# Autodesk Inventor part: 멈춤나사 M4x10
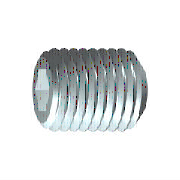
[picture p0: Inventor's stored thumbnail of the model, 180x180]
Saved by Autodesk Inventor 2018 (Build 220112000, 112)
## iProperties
Created: 2012-02
Part Number: 멈춤나사 M4x10
Material: 강철, 연강
Description: 6각 소켓 머리 없는 멈춤 나사
Document SubType Name: Modeling
Standard: KS B 1028
Designer: mduedu
Standards Organization: KS
Language: ko-KR
Size Designation: 납작점M4x10
Categories: <MemberInstance><Categories><Category DisplayName="조임쇠" InternalName="e4da775c-781d-43d5-af7c-5136215cf5a6" Mnemonic="FSTN"><Category DisplayName="볼트" InternalN
Density: 1 g/cm^3
Appearance: Steel
IsCustomPart: 1
Author: mduedu
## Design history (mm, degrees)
sketch "스케치1"
  geometry: L1 (0, 0)-(6.833, 0); L2 (10, 1.155)-(10, 2); L3 (10, 2)-(0, 2); L4 (10, 1.155)-(7.5, 1.155); L5 (7.5, 1.155)-(6.833, 0); L6 (0, -0.4)-(0, 2.4) reference; L7 (0, 2)-(0, 0)
  constraints: 13 end point, 3 parallel, 1 collinear, 1 perpendicular, 1 point on line
  dimensions: "d0" = 2.5 distance of L2.start L4.end (= INTI); "d1" = 60 deg angle of L5 L1; "d2" = 4 diameter of L3 L1 (= NND); "d3" = 2.3094 diameter of L4 L1 (= 1.1547 x SW); "d5" = 10 distance from line of L2 L3.end (= NLG)
revolve "본체" sketch "스케치1" stored, may be unused: angle "d6" = 90 deg
sketch "스케치2"
  geometry: L1 (-0.577, 1)-(0.577, 1); L2 (0.577, 1)-(1.155, 0); L3 (1.155, 0)-(0.577, -1); L4 (0.577, -1)-(-0.577, -1); L5 (-0.577, -1)-(-1.155, 0); L6 (-1.155, 0)-(-0.577, 1); A1 r 1.155 centre (0, 0) between (-0.577, 1) and (0.577, 1) reference; 2 further points
  constraints: 12 end point, 2 point on circle, 1 coincident, 1 horizontal, 11 other
extrude "슬롯" join sketch "스케치2" taper "d9" = 0 deg; stored distance "d21" = 10
workaxis "Work Axis1"
workplane "Work Plane1"
body "Solid1"
chamfer "모따기1" distance "d7" = 0.42941 (= -0.5 x GD1 + 0.5 x NND); stored, may be unused: angle "d8" = 45 deg (= FAWI), second distance "d29" = 0.42941 (= -0.5 x GD1 + 0.5 x NND)
feature "스레드" dims "d11" = 10 (= NLG), "d12" = 0
chamfer "모따기2" distance "d13" = 0.42941 (= -0.5 x GD1 + 0.5 x NND); stored, may be unused: angle "d14" = 45 deg (= FAWI), second distance "d30" = 0.42941 (= -0.5 x GD1 + 0.5 x NND)
other parameters: "NND" = 4 [user parameter; used in 5 equation terms], "NLG" = 10 [user parameter; used in 2 equation terms], "INTI" = 2.5 [user parameter; used in 1 equation term], "FAWI" = 45 deg [user parameter; used in 2 equation terms], "SW" = 2 [user parameter; used in 2 equation terms], "GD1" = 3.14117 (= THREADDIA - 1.2269 x PTC) [user parameter; used in 4 equation terms], "d4" = 0, "FAWI1" = 45 deg [user parameter], "d15" = 0, "d31" = 0, "GUL" = 0.42941 (= 0.61345 x PTC) [user parameter], "SPD" = 2.5 [user parameter], "TPU" = 14.28571 (computed from PTC) [user parameter], "TOA" = 30 deg [user parameter], "THREADDIA" = 4 [user parameter; used in 1 equation term], "PTC" = 0.7 [user parameter; used in 4 equation terms], "GAL" = 0.42941 (= 0.61345 x PTC) [user parameter], "E0" = 2.31 (= 1.155 x SW) [user parameter]
